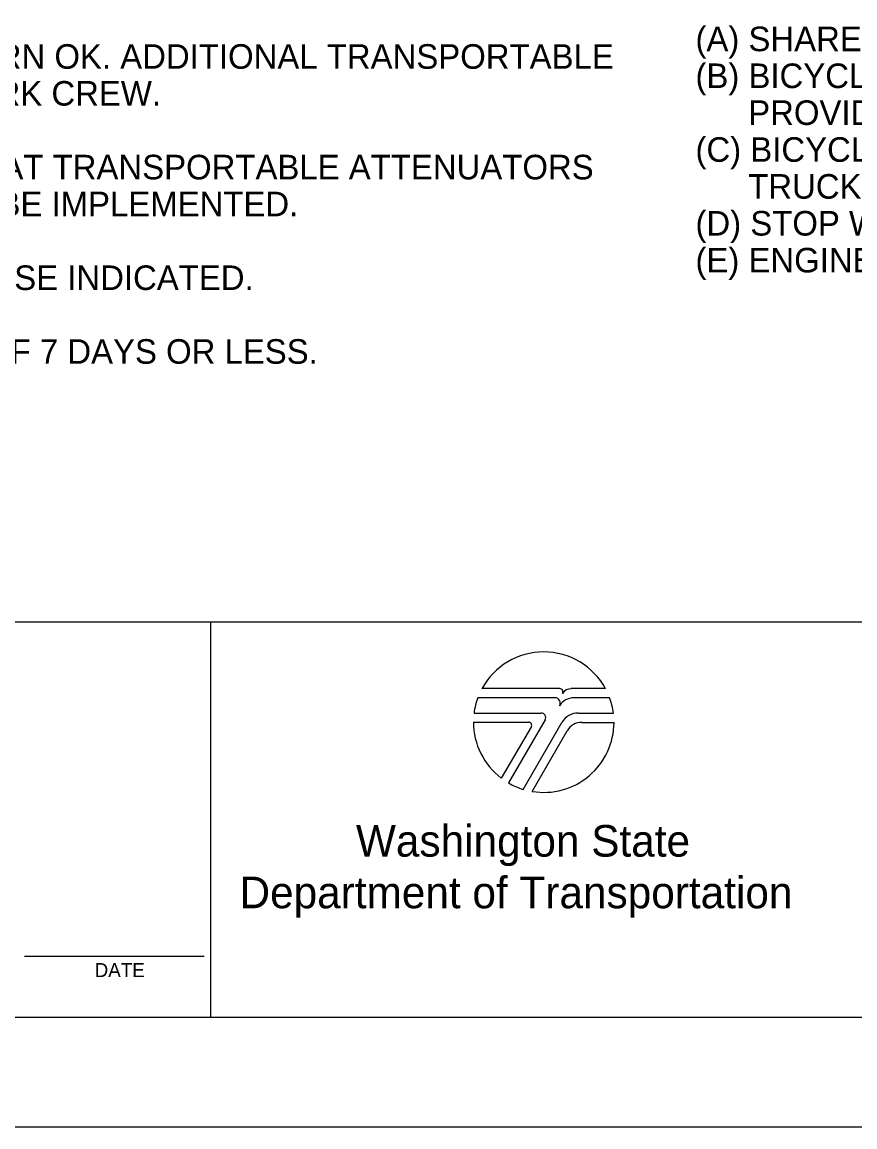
# Model space of a CAD drawing. Extents: x 99999.1 to 100055.7, y 99995 to 100013.2.
# Drawn here: x 100009.773 to 100012.143, y 99999.687 to 100002.833 of the extents above; entities that cross this region are included whole.
import ezdxf

# ---------------------------------------------------------------- set-up
doc = ezdxf.new("R2010")
doc.units = 0
for name, color, linetype in [('SH_GI_GeneralNotesBodyText', 7, 'Continuous'), ('SH_GI_PlotLimits', 7, 'Continuous'), ('SH_GI_SheetBorder', 7, 'Continuous'), ('SH_GI_SheetTextInCells', 7, 'Continuous'), ('SH_GI_WSDOTLogo', 7, 'Continuous')]:
    doc.layers.add(name, color=color, linetype=linetype)

msp = doc.modelspace()

# ---------------------------------------------------------------- linework, layer by layer
at = {"layer": 'SH_GI_PlotLimits'}
msp.add_lwpolyline([(99999.0625, 99999.6875), (100016.0625, 99999.6875), (100016.0625, 100010.6875), (99999.0625, 100010.6875)], close=True, dxfattribs=at)
at = {"layer": 'SH_GI_SheetBorder'}
for p, q in [((100000, 100001.1259), (100015.75, 100001.1259)), ((100010.3089, 100001.1259), (100010.3089, 100000)), ((100009.7797, 100000.1733), (100010.2914, 100000.1733)), ((100000, 100000), (100015.75, 100000))]:
    msp.add_line(p, q, dxfattribs=at)
at = {"layer": 'SH_GI_WSDOTLogo'}
for p, q in [((100011.2894, 100000.9094), (100011.0697, 100000.9094)), ((100011.303, 100000.9354), (100011.0815, 100000.9354)), ((100011.433, 100000.9354), (100011.3351, 100000.9354)), ((100011.343, 100000.9094), (100011.3429, 100000.9094)), ((100011.4448, 100000.9094), (100011.343, 100000.9094)), ((100011.059, 100000.8661), (100011.2496, 100000.8661)), ((100011.261, 100000.8464), (100011.1567, 100000.6672)), ((100011.3558, 100000.8661), (100011.4555, 100000.8661)), ((100011.0572, 100000.84), (100011.2148, 100000.84)), ((100011.222, 100000.8277), (100011.1364, 100000.6807)), ((100011.1989, 100000.6487), (100011.3089, 100000.839)), ((100011.2244, 100000.6428), (100011.3242, 100000.8156)), ((100011.3655, 100000.8394), (100011.4572, 100000.8394))]:
    msp.add_line(p, q, dxfattribs=at)
for centre, radius, start, end in [((100011.2572, 100000.84), 0.2, 28.4787, 151.532), ((100011.2572, 100000.84), 0.2, 159.696, 172.5057), ((100011.2894, 100000.8946), 0.0148, 327.8418, 89.9985), ((100011.3429, 100000.861), 0.0484, 89.9953, 147.8238), ((100011.303, 100000.9263), 0.00903, 329.8742, 90.0033), ((100011.3352, 100000.9066), 0.0287, 90.0072, 148.1676), ((100011.2572, 100000.84), 0.2, 7.4943, 20.2941), ((100011.2497, 100000.853), 0.0131, 329.7683, 90), ((100011.3558, 100000.8119), 0.0542, 90, 149.9974), ((100011.2572, 100000.84), 0.2, 179.9986, 232.8433), ((100011.2149, 100000.8318), 0.0082, 329.7436, 90), ((100011.2572, 100000.84), 0.2, 260.5455, 359.8086), ((100011.3654, 100000.7918), 0.0476, 90, 150.0543), ((100011.2572, 100000.84), 0.2, 239.7929, 253.0448)]:
    msp.add_arc(centre, radius, start, end, dxfattribs=at)

# ---------------------------------------------------------------- texts
at = {"layer": 'SH_GI_GeneralNotesBodyText'}
for s, p in [('(A) SHARED BICYCLE-VEHICLE LANE. ADD W11-15 MOD & R4-11 SIGNS.', (100011.689, 100002.7506)), ('5. RED/WHITE OR BLACK/YELLOW CHEVRON PATTERN OK. ADDITIONAL TRANSPORTABLE ', (100007.3371, 100002.7006)), ('(B) BICYCLES PROHIBITED VIA R5-601 (IF EXIT-RAMP PRESENT) & R5-6 SIGNS. ', (100011.689, 100002.6456)), ('ATTENUATORS MAY BE ADDED BEHIND EACH WORK CREW.', (100007.4171, 100002.5956)), ('PROVIDE SIGNED DETOUR OR ALTERNATIVE ROUTE.', (100011.839, 100002.5406)), ('(C) BICYCLES PROHIBITED VIA R5-6 SIGN(S). PROVIDE FREE SHUTTLE (WORK ', (100011.689, 100002.4356)), ('6. IF PAVED SHOULDER IS LESS THAN 8 FEET WIDE AT TRANSPORTABLE ATTENUATORS ', (100007.3371, 100002.3856)), ('TRUCK, VAN, OR BUS OK) + CONTACT INFORMATION/PHONE BOX/LABORER. ', (100011.839, 100002.3306)), ('AND WORK AREA, THEN A LANE CLOSURE SHALL BE IMPLEMENTED.', (100007.4171, 100002.2806)), ('(D) STOP WORK OPS. & ESCORT BICYCLISTS THROUGH SHOULDER CLOSURE.', (100011.689, 100002.2256)), ('(E) ENGINEER TO ACCEPT ANY ALTERNATIVE STRATEGIES.', (100011.689, 100002.1206)), ('7. SIGNS ARE BLACK ON ORANGE UNLESS OTHERWISE INDICATED.', (100007.3371, 100002.0706)), ('8. PLAN IS APPLICABLE TO SHOULDER CLOSURES OF 7 DAYS OR LESS.', (100007.3371, 100001.8606))]:
    msp.add_text(s, height=0.07, rotation=360, dxfattribs=at).set_placement(p)
at = {"layer": 'SH_GI_SheetTextInCells'}
for s, height, p in [('Washington State', 0.090072, (100010.7229, 100000.4571)), ('Department of Transportation', 0.090072, (100010.3916, 100000.3101)), ('DATE', 0.04003, (100009.9794, 100000.1141))]:
    msp.add_text(s, height=height, dxfattribs=at).set_placement(p)

doc.saveas('drawing.dxf')
